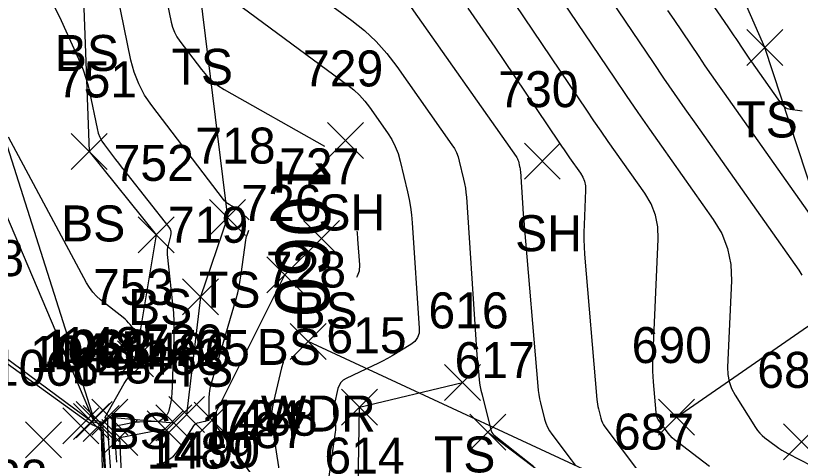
# Model space of a CAD drawing. Extents: x 1592612 to 1596497, y 111838 to 113741.
# Drawn here: x 1592882.21 to 1592925.84, y 113458.7 to 113483.39 of the extents above; entities that cross this region are included whole.
import ezdxf

# ---------------------------------------------------------------- set-up
doc = ezdxf.new("R2010")
doc.units = 0
for name, color, linetype in [('L_A', 7, 'Continuous'), ('L_I', 7, 'Continuous'), ('L_TIC', 7, 'Continuous'), ('LAWA', 7, 'Continuous'), ('LAWE', 7, 'Continuous'), ('LELB', 7, 'Continuous'), ('LSOGCMA', 7, 'Continuous'), ('LSOGCMA_T', 7, 'Continuous'), ('LSOGCMI', 7, 'Continuous'), ('LW', 7, 'Continuous')]:
    doc.layers.add(name, color=color, linetype=linetype)

msp = doc.modelspace()

# ---------------------------------------------------------------- linework, layer by layer
at = {"layer": 'L_TIC'}
for points in [[(1592922.872, 113480.628), (1592924.872, 113482.628)], [(1592924.872, 113480.628), (1592922.872, 113482.628)], [(1592899.557, 113475.462), (1592901.557, 113477.462)], [(1592901.557, 113475.462), (1592899.557, 113477.462)], [(1592885.296, 113474.852), (1592887.296, 113476.852)], [(1592887.296, 113474.852), (1592885.296, 113476.852)], [(1592910.494, 113474.31), (1592912.494, 113476.31)], [(1592912.494, 113474.31), (1592910.494, 113476.31)], [(1592892.995, 113471.176), (1592894.995, 113473.176)], [(1592894.995, 113471.176), (1592892.995, 113473.176)], [(1592889.02, 113470.216), (1592891.02, 113472.216)], [(1592891.02, 113470.216), (1592889.02, 113472.216)], [(1592898.22, 113470.022), (1592900.22, 113472.022)], [(1592900.22, 113470.022), (1592898.22, 113472.022)], [(1592896.172, 113467.993), (1592898.172, 113469.993)], [(1592898.172, 113467.993), (1592896.172, 113469.993)], [(1592891.484, 113466.779), (1592893.484, 113468.779)], [(1592893.484, 113466.779), (1592891.484, 113468.779)], [(1592897.481, 113464.293), (1592899.481, 113466.293)], [(1592899.481, 113464.293), (1592897.481, 113466.293)], [(1592887.879, 113463.325), (1592889.879, 113465.325)], [(1592889.879, 113463.325), (1592887.879, 113465.325)], [(1592906.058, 113462.022), (1592908.058, 113464.022)], [(1592908.058, 113462.022), (1592906.058, 113464.022)], [(1592900.328, 113460.642), (1592902.328, 113462.642)], [(1592902.328, 113460.642), (1592900.328, 113462.642)], [(1592885.43, 113459.851), (1592887.43, 113461.851)], [(1592887.43, 113459.851), (1592885.43, 113461.851)], [(1592885.583, 113459.952), (1592887.583, 113461.952)], [(1592887.583, 113459.952), (1592885.583, 113461.952)], [(1592886.442, 113460.092), (1592888.442, 113462.092)], [(1592888.442, 113460.092), (1592886.442, 113462.092)], [(1592890.718, 113460.24), (1592892.718, 113462.24)], [(1592892.718, 113460.24), (1592890.718, 113462.24)], [(1592892.135, 113459.931), (1592894.135, 113461.931)], [(1592894.135, 113459.931), (1592892.135, 113461.931)], [(1592917.957, 113460.097), (1592919.957, 113462.097)], [(1592919.957, 113460.097), (1592917.957, 113462.097)], [(1592884.837, 113459.607), (1592886.837, 113461.607)], [(1592886.837, 113459.607), (1592884.837, 113461.607)], [(1592885.972, 113459.742), (1592887.972, 113461.742)], [(1592887.972, 113459.742), (1592885.972, 113461.742)], [(1592889.521, 113459.444), (1592891.521, 113461.444)], [(1592891.521, 113459.444), (1592889.521, 113461.444)], [(1592890.003, 113459.781), (1592892.003, 113461.781)], [(1592892.003, 113459.781), (1592890.003, 113461.781)], [(1592907.461, 113459.258), (1592909.461, 113461.258)], [(1592909.461, 113459.258), (1592907.461, 113461.258)], [(1592882.761, 113458.833), (1592884.761, 113460.833)], [(1592884.761, 113458.833), (1592882.761, 113460.833)], [(1592887, 113458.963), (1592889, 113460.963)], [(1592889, 113458.963), (1592887, 113460.963)], [(1592924.91, 113458.718), (1592926.91, 113460.718)], [(1592926.91, 113458.718), (1592924.91, 113460.718)]]:
    msp.add_lwpolyline(points, dxfattribs=at)
at = {"layer": 'LAWA'}
msp.add_lwpolyline([(1592917.884, 113456.286), (1592898.481, 113465.293)], dxfattribs=at)
at = {"layer": 'LAWE'}
for points in [[(1592886.537, 113460.922), (1592877.744, 113481.574), (1592863.095, 113501.144), (1592852.902, 113518.209), (1592848.805, 113541.382), (1592835.879, 113571.623), (1592826.212, 113589.998), (1592821.08, 113603.103), (1592811.502, 113625.047), (1592801.909, 113656.496), (1592787.746, 113677.481), (1592769.551, 113701.793), (1592752.509, 113717.946)], [(1592887.05, 113460.8), (1592886.537, 113460.922)], [(1592887.496, 113453.354), (1592887.05, 113460.8)]]:
    msp.add_lwpolyline(points, dxfattribs=at)
at = {"layer": 'LELB'}
for points in [[(1592886.583, 113460.952), (1592879.778, 113482.315), (1592863.966, 113501.755), (1592853.366, 113518.29), (1592851.192, 113542.037), (1592841.019, 113567.093), (1592831.516, 113591.894), (1592821.816, 113602.808), (1592813.329, 113624.79), (1592804.232, 113657.067), (1592789.644, 113678.369), (1592770.935, 113703.549), (1592752.623, 113718.428)], [(1592886.43, 113460.851), (1592879.543, 113465.926), (1592876.137, 113481.194), (1592862.304, 113500.643), (1592852.529, 113517.932), (1592848.162, 113540.894), (1592835.177, 113571.255), (1592825.196, 113589.927), (1592820.421, 113603.303), (1592810.027, 113625.391), (1592799.468, 113655.332), (1592786.607, 113676.744), (1592768.899, 113700.806), (1592752.213, 113717.027)], [(1592885.411, 113547.376), (1592876.234, 113539.25), (1592867.617, 113532.911), (1592863.38, 113520.43), (1592865.405, 113513.944), (1592869.075, 113508.737), (1592880.629, 113500.08), (1592889.409, 113493.364), (1592892.469, 113484.552), (1592893.995, 113472.176), (1592892.484, 113467.779), (1592891.718, 113461.24)], [(1592853.127, 113529.053), (1592857.59, 113521.31), (1592858.606, 113515.284), (1592868.403, 113504.739), (1592877.011, 113497.321), (1592880.268, 113489.72), (1592885.949, 113485.322), (1592886.296, 113475.852), (1592890.02, 113471.216), (1592888.879, 113464.325)], [(1592918.957, 113461.096), (1592928.472, 113467.665), (1592923.872, 113481.628), (1592916.743, 113497.854), (1592906.203, 113506.134), (1592893.782, 113529.323)], [(1592911.437, 113445.994), (1592905.315, 113449.795), (1592898.185, 113451.855), (1592895.983, 113457.019), (1592893.134, 113460.931), (1592897.172, 113468.993), (1592899.22, 113471.022)], [(1592912.798, 113444.415), (1592913.686, 113447.658), (1592909.676, 113451.222), (1592901.218, 113454.954), (1592901.328, 113461.643), (1592907.058, 113463.022)], [(1592886.43, 113460.851), (1592886.972, 113460.742)], [(1592908.46, 113460.258), (1592922.596, 113449.566), (1592933.267, 113441.549), (1592945.1, 113436.529), (1592970.28, 113425.515), (1592997.076, 113416.402), (1593023.641, 113407.833), (1593049.418, 113399.686), (1593079.204, 113391.835), (1593097.266, 113387.672), (1593130.658, 113380.878), (1593168.554, 113372.43)]]:
    msp.add_lwpolyline(points, dxfattribs=at)
at = {"layer": 'LSOGCMA'}
for points in [[(1592920.796, 113458.356), (1592918.967, 113459.732), (1592918.837, 113459.837), (1592918.715, 113459.951), (1592918.601, 113460.073), (1592918.496, 113460.204), (1592917.931, 113460.956), (1592917.912, 113460.984), (1592917.896, 113461.014), (1592917.882, 113461.046), (1592917.872, 113461.079), (1592917.838, 113461.213), (1592917.83, 113461.247), (1592917.824, 113461.281), (1592917.819, 113461.315), (1592917.815, 113461.35), (1592917.672, 113463.05), (1592917.652, 113463.344), (1592917.641, 113463.64), (1592917.64, 113463.935), (1592917.648, 113464.23), (1592917.941, 113470.974), (1592917.917, 113471.66), (1592917.784, 113472.315), (1592917.541, 113472.937), (1592917.19, 113473.528), (1592915.564, 113475.825), (1592915.159, 113476.4), (1592914.758, 113476.978), (1592914.36, 113477.557), (1592913.965, 113478.14), (1592906.498, 113489.218)], [(1592890.617, 113484.201), (1592890.858, 113483.034), (1592890.933, 113482.749), (1592891.038, 113482.478), (1592891.174, 113482.221), (1592891.34, 113481.977), (1592892.543, 113480.402), (1592892.818, 113480.076), (1592893.122, 113479.784), (1592893.453, 113479.523), (1592893.813, 113479.295), (1592899.386, 113476.143)], [(1592901.183, 113471.432), (1592901.194, 113471.345), (1592901.225, 113470.987), (1592901.321, 113469.548), (1592901.303, 113469.21), (1592901.202, 113468.916), (1592901.16, 113468.858)], [(1592897.101, 113464.163), (1592897.088, 113464.125), (1592896.995, 113463.825), (1592896.916, 113463.52), (1592896.543, 113461.943), (1592896.475, 113461.577), (1592896.443, 113461.21), (1592896.447, 113460.841), (1592896.487, 113460.471), (1592896.861, 113458.091)]]:
    msp.add_lwpolyline(points, dxfattribs=at)
at = {"layer": 'LSOGCMI'}
for points in [[(1592925.947, 113478.098), (1592925.811, 113478.113), (1592925.266, 113478.187), (1592925.136, 113478.218), (1592925.022, 113478.272), (1592924.921, 113478.349), (1592924.834, 113478.449), (1592923.152, 113480.826), (1592923.039, 113480.986), (1592922.928, 113481.147), (1592922.817, 113481.308), (1592922.707, 113481.47), (1592922.27, 113482.119), (1592922.16, 113482.281), (1592922.051, 113482.442), (1592921.94, 113482.604), (1592921.83, 113482.765), (1592913.649, 113494.65)], [(1592910.938, 113486.705), (1592915.515, 113479.915), (1592916.158, 113478.967), (1592916.806, 113478.024), (1592917.459, 113477.084), (1592918.118, 113476.147), (1592921, 113472.074), (1592921.47, 113471.286), (1592921.794, 113470.455), (1592921.972, 113469.58), (1592922.004, 113468.663), (1592921.796, 113463.872), (1592921.808, 113463.459), (1592921.881, 113463.063), (1592922.015, 113462.683), (1592922.21, 113462.319), (1592923.353, 113460.513), (1592923.463, 113460.354), (1592923.587, 113460.208), (1592923.723, 113460.073), (1592923.873, 113459.949), (1592924.495, 113459.481), (1592924.653, 113459.367), (1592924.816, 113459.26), (1592924.982, 113459.161), (1592925.153, 113459.068), (1592927.74, 113457.736)], [(1592897.987, 113485.282), (1592900.9, 113483.131), (1592901.602, 113482.567), (1592902.253, 113481.954), (1592902.852, 113481.29), (1592903.4, 113480.575), (1592906.466, 113476.226), (1592906.603, 113476.012), (1592906.717, 113475.789), (1592906.809, 113475.555), (1592906.879, 113475.312), (1592907.116, 113474.319), (1592907.17, 113474.07), (1592907.214, 113473.819), (1592907.247, 113473.567), (1592907.269, 113473.313), (1592907.776, 113465.679), (1592907.795, 113465.397), (1592907.816, 113465.116), (1592907.838, 113464.835), (1592907.861, 113464.554), (1592907.955, 113463.431), (1592907.985, 113463.151), (1592908.026, 113462.873), (1592908.078, 113462.597), (1592908.142, 113462.323), (1592908.653, 113460.319), (1592908.66, 113460.297), (1592908.668, 113460.276), (1592908.679, 113460.256), (1592908.692, 113460.237), (1592908.748, 113460.162), (1592908.763, 113460.144), (1592908.779, 113460.127), (1592908.795, 113460.111), (1592908.813, 113460.096), (1592911.02, 113458.343)], [(1592895.188, 113472.044), (1592894.785, 113472.444), (1592894.708, 113472.516), (1592894.625, 113472.582), (1592894.539, 113472.643), (1592894.449, 113472.699), (1592894.078, 113472.908), (1592893.988, 113472.965), (1592893.906, 113473.029), (1592893.831, 113473.102), (1592893.763, 113473.183), (1592889.773, 113478.405), (1592889.377, 113478.986), (1592889.053, 113479.601), (1592888.802, 113480.248), (1592888.622, 113480.928), (1592887.87, 113484.574)], [(1592894.019, 113484.456), (1592900.677, 113479.539), (1592901.016, 113479.267), (1592901.33, 113478.971), (1592901.619, 113478.651), (1592901.884, 113478.306), (1592902.891, 113476.877), (1592903.124, 113476.512), (1592903.319, 113476.129), (1592903.477, 113475.73), (1592903.597, 113475.313), (1592904.003, 113473.614), (1592904.096, 113473.188), (1592904.17, 113472.759), (1592904.226, 113472.327), (1592904.264, 113471.892), (1592904.653, 113466.038), (1592904.638, 113465.755), (1592904.554, 113465.509), (1592904.399, 113465.299), (1592904.175, 113465.126), (1592903.139, 113464.507), (1592902.878, 113464.355), (1592902.614, 113464.21), (1592902.346, 113464.072), (1592902.075, 113463.94), (1592900.579, 113463.235), (1592900.416, 113463.137), (1592900.286, 113463.011), (1592900.19, 113462.858), (1592900.127, 113462.678), (1592899.911, 113461.763), (1592899.888, 113461.639), (1592899.877, 113461.513), (1592899.879, 113461.388), (1592899.892, 113461.262), (1592899.972, 113460.756), (1592899.987, 113460.63), (1592899.992, 113460.503), (1592899.989, 113460.377), (1592899.975, 113460.25), (1592899.401, 113456.242)], [(1592903.982, 113484.169), (1592910.042, 113475.575), (1592910.081, 113475.513), (1592910.114, 113475.448), (1592910.141, 113475.381), (1592910.161, 113475.311), (1592910.23, 113475.024), (1592910.245, 113474.952), (1592910.258, 113474.88), (1592910.267, 113474.807), (1592910.274, 113474.734), (1592910.389, 113472.995), (1592910.411, 113472.681), (1592910.434, 113472.367), (1592910.458, 113472.053), (1592910.484, 113471.739), (1592911.236, 113462.808), (1592911.261, 113462.575), (1592911.295, 113462.343), (1592911.338, 113462.113), (1592911.391, 113461.885), (1592911.623, 113460.975), (1592911.692, 113460.752), (1592911.781, 113460.54), (1592911.891, 113460.337), (1592912.021, 113460.144), (1592913.094, 113458.716), (1592913.328, 113458.424)], [(1592925.947, 113468.971), (1592925.778, 113469.255), (1592920.041, 113477.361), (1592919.442, 113478.212), (1592918.848, 113479.066), (1592918.259, 113479.924), (1592917.675, 113480.785), (1592915.349, 113484.236)], [(1592884.376, 113483.875), (1592884.645, 113483.333), (1592885.79, 113480.788), (1592885.955, 113480.391), (1592886.099, 113479.986), (1592886.219, 113479.574), (1592886.318, 113479.156), (1592886.738, 113477.119), (1592886.802, 113476.875), (1592886.892, 113476.643), (1592887.008, 113476.423), (1592887.15, 113476.215), (1592887.768, 113475.406), (1592887.923, 113475.204), (1592888.079, 113475.002), (1592888.235, 113474.801), (1592888.393, 113474.601), (1592890.727, 113471.639), (1592890.795, 113471.53), (1592890.834, 113471.415), (1592890.843, 113471.295), (1592890.823, 113471.168), (1592890.683, 113470.649), (1592890.654, 113470.519), (1592890.637, 113470.387), (1592890.633, 113470.255), (1592890.641, 113470.122), (1592890.934, 113467.395), (1592890.978, 113466.895), (1592891.005, 113466.395), (1592891.013, 113465.895), (1592891.002, 113465.394), (1592890.886, 113462.373), (1592890.879, 113462.263), (1592890.868, 113462.155), (1592890.852, 113462.047), (1592890.831, 113461.939), (1592890.728, 113461.457), (1592890.706, 113461.38), (1592890.672, 113461.309), (1592890.628, 113461.244), (1592890.573, 113461.185), (1592890.33, 113460.962), (1592890.266, 113460.913), (1592890.197, 113460.877), (1592890.123, 113460.854), (1592890.044, 113460.845), (1592889.089, 113460.814), (1592888.949, 113460.806), (1592888.808, 113460.792), (1592888.669, 113460.772), (1592888.53, 113460.745), (1592887.785, 113460.586), (1592887.748, 113460.573), (1592887.722, 113460.551), (1592887.707, 113460.521), (1592887.702, 113460.482), (1592887.703, 113460.31), (1592887.704, 113460.267), (1592887.705, 113460.224), (1592887.707, 113460.181), (1592887.71, 113460.138), (1592887.816, 113458.594)], [(1592907.351, 113483.81), (1592907.856, 113483.09), (1592908.358, 113482.367), (1592908.855, 113481.641), (1592909.349, 113480.912), (1592912.414, 113476.365), (1592912.562, 113476.148), (1592912.71, 113475.932), (1592912.86, 113475.716), (1592913.01, 113475.502), (1592913.616, 113474.646), (1592913.747, 113474.426), (1592913.838, 113474.194), (1592913.887, 113473.95), (1592913.896, 113473.694), (1592913.813, 113471.775), (1592913.802, 113471.368), (1592913.803, 113470.962), (1592913.818, 113470.555), (1592913.846, 113470.149), (1592914.525, 113462.079), (1592914.54, 113461.945), (1592914.559, 113461.812), (1592914.584, 113461.68), (1592914.615, 113461.549), (1592914.748, 113461.027), (1592914.787, 113460.899), (1592914.838, 113460.777), (1592914.901, 113460.661), (1592914.976, 113460.55), (1592917.908, 113456.645)], [(1592918.463, 113483.69), (1592918.809, 113483.177), (1592920.191, 113481.127), (1592920.538, 113480.616), (1592920.888, 113480.106), (1592921.241, 113479.599), (1592921.596, 113479.093), (1592926.914, 113471.581)], [(1592887.63, 113456.24), (1592887.34, 113460.438), (1592887.336, 113460.495), (1592887.334, 113460.552), (1592887.332, 113460.608), (1592887.331, 113460.665), (1592887.329, 113460.966), (1592887.326, 113460.985), (1592887.319, 113461), (1592887.306, 113461.01), (1592887.288, 113461.017), (1592887.208, 113461.037), (1592887.192, 113461.044), (1592887.183, 113461.054), (1592887.182, 113461.067), (1592887.188, 113461.083), (1592888.249, 113462.967), (1592888.316, 113463.077), (1592888.392, 113463.18), (1592888.475, 113463.277), (1592888.566, 113463.367), (1592889.115, 113463.871), (1592889.126, 113463.882), (1592889.134, 113463.895), (1592889.14, 113463.908), (1592889.145, 113463.923), (1592889.158, 113463.984), (1592889.161, 113463.999), (1592889.163, 113464.015), (1592889.165, 113464.03), (1592889.166, 113464.046), (1592889.182, 113464.469), (1592889.183, 113464.545), (1592889.182, 113464.621), (1592889.178, 113464.696), (1592889.172, 113464.772), (1592889.111, 113465.335), (1592889.091, 113465.451), (1592889.055, 113465.561), (1592889.004, 113465.665), (1592888.939, 113465.762), (1592888.573, 113466.232), (1592888.485, 113466.339), (1592888.39, 113466.44), (1592888.29, 113466.535), (1592888.184, 113466.625), (1592886.936, 113467.613), (1592886.704, 113467.817), (1592886.496, 113468.041), (1592886.312, 113468.285), (1592886.153, 113468.55), (1592881.816, 113476.647)], [(1592889.991, 113458.304), (1592890.676, 113458.699), (1592890.84, 113458.807), (1592890.987, 113458.931), (1592891.119, 113459.071), (1592891.234, 113459.229), (1592892.125, 113460.604), (1592892.181, 113460.676), (1592892.247, 113460.733), (1592892.324, 113460.774), (1592892.411, 113460.801), (1592892.95, 113460.917), (1592892.955, 113460.919), (1592892.959, 113460.922), (1592892.961, 113460.926), (1592892.962, 113460.932), (1592892.962, 113460.969), (1592892.962, 113460.981), (1592892.974, 113462.18), (1592892.982, 113462.381), (1592893.005, 113462.58), (1592893.041, 113462.777), (1592893.091, 113462.972), (1592894.463, 113467.667), (1592894.555, 113468.006), (1592894.634, 113468.348), (1592894.701, 113468.693), (1592894.754, 113469.04), (1592895.01, 113470.932), (1592895.026, 113471.032), (1592895.05, 113471.129), (1592895.08, 113471.225), (1592895.117, 113471.318), (1592895.183, 113471.47)], [(1592880.053, 113465.278), (1592886.206, 113460.843), (1592886.242, 113460.818), (1592886.278, 113460.795), (1592886.315, 113460.773), (1592886.353, 113460.752), (1592886.506, 113460.672), (1592886.544, 113460.652), (1592886.583, 113460.632), (1592886.621, 113460.612), (1592886.66, 113460.592), (1592886.882, 113460.477), (1592886.926, 113460.448), (1592886.959, 113460.411), (1592886.98, 113460.366), (1592886.989, 113460.314), (1592887.358, 113455.055)]]:
    msp.add_lwpolyline(points, dxfattribs=at)
at = {"layer": 'LW'}
for points in [[(1592891.001, 113425.248), (1592889.479, 113425.239), (1592888.769, 113433.154), (1592888.646, 113438.569), (1592887.709, 113444.489), (1592887.193, 113453.339), (1592886.972, 113460.742), (1592887.442, 113461.092), (1592891.003, 113460.781)], [(1592891.04, 113425.998), (1592889.85, 113425.876), (1592890.051, 113429.468), (1592890.075, 113433.042), (1592889.594, 113438.427), (1592888.881, 113444.687), (1592888.324, 113453.144), (1592888, 113459.963), (1592890.521, 113460.444)]]:
    msp.add_lwpolyline(points, dxfattribs=at)

# ---------------------------------------------------------------- texts
at = {"layer": 'L_A'}
for s, p in [('BS', (1592884.389, 113480.322)), ('TS', (1592890.878, 113479.552)), ('TS', (1592922.281, 113476.628)), ('SH', (1592899.046, 113471.462)), ('BS', (1592884.737, 113470.852)), ('SH', (1592909.982, 113470.31)), ('TS', (1592892.405, 113467.176)), ('BS', (1592888.461, 113466.216)), ('BS', (1592897.661, 113466.022)), ('BS', (1592895.613, 113463.993)), ('TS', (1592890.893, 113462.779)), ('WDR', (1592895.844, 113460.293)), ('BS', (1592887.32, 113459.325)), ('TS', (1592905.467, 113458.022))]:
    msp.add_text(s, height=2, dxfattribs=at).set_placement(p)
at = {"layer": 'L_I'}
for s, p in [('729', (1592898.187, 113479.462)), ('751', (1592884.5, 113478.852)), ('730', (1592909.045, 113478.31)), ('718', (1592892.2, 113475.176)), ('752', (1592887.657, 113474.216)), ('727', (1592896.858, 113474.022)), ('726', (1592894.755, 113471.993)), ('719', (1592890.68, 113470.779)), ('1068', (1592876.725, 113468.926)), ('728', (1592896.119, 113468.293)), ('753', (1592886.517, 113467.325)), ('616', (1592905.16, 113466.022)), ('615', (1592899.486, 113464.642)), ('720', (1592889.269, 113464.24)), ('1065', (1592883.611, 113463.851)), ('1063', (1592883.764, 113463.952)), ('1485', (1592884.749, 113464.092)), ('1486', (1592888.255, 113463.781)), ('725', (1592890.772, 113463.931)), ('690', (1592916.461, 113464.097)), ('1064', (1592883.018, 113463.607)), ('1484', (1592884.279, 113463.742)), ('1483', (1592887.828, 113463.444)), ('1482', (1592885.307, 113462.963)), ('617', (1592906.618, 113463.258)), ('1066', (1592880.887, 113462.833)), ('686', (1592923.445, 113462.718)), ('1488', (1592893.055, 113460.06)), ('724', (1592893.62, 113460.019)), ('1487', (1592892.497, 113459.371)), ('687', (1592915.475, 113459.286)), ('1489', (1592889.5, 113458.23)), ('1490', (1592889.846, 113458.306)), ('614', (1592899.376, 113457.954)), ('1238', (1592878.031, 113456.73))]:
    msp.add_text(s, height=2, dxfattribs=at).set_placement(p)
at = {"layer": 'LSOGCMA_T'}
msp.add_text('1060', height=3, rotation=269.4872, dxfattribs=at).set_placement((1592896.72, 113475.6))

doc.saveas('drawing.dxf')
